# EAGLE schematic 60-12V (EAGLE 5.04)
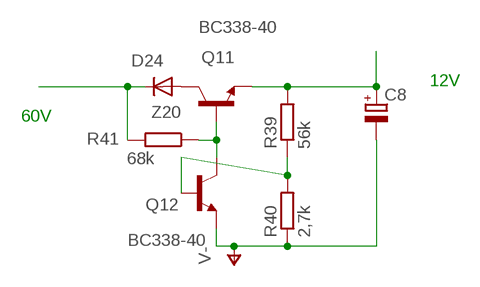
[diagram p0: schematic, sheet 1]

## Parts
C8  CPOL-EU5-13  [2,5-5-FLAT]
D24  Z20  DIODE-D-7.5  [D-7.5]
Q11  BC338-40  [TO92-EBC]
Q12  BC338-40  [TO92-EBC]
R39  56k  R-EU_0207/10  [0207/10]
R40  2,7k  R-EU_0204/2V  [0204V]
R41  68k  R-EU_0207/10  [0207/10]

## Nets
N$36: D24.A Q11.C
N$38: Q11.B Q12.C R41.1
N$41: Q12.B R39.1 R40.2
V-: C8.- Q12.E R40.1
VCC: C8.+ Q11.E R39.2
VIN: D24.C R41.2

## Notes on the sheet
- 12V
- 60V

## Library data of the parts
C8 = rcl-2:CPOL-EU: POLARIZED CAPACITOR, European symbol
D24 = diode-1:DIODE-: DIODE
Q11 Q12 = transistor-npn:BC338*: NPN Transistor
R39-R41 = rcl-2:R-EU_: RESISTOR, European symbol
